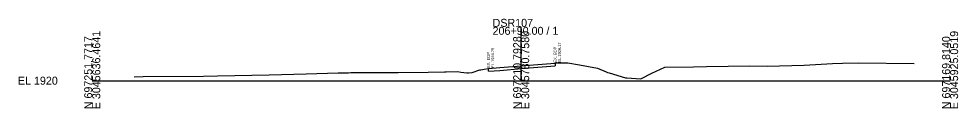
# Model space of a CAD drawing. Extents: x -26 to 19003, y -31 to 24541.
# Drawn here: x 1974.3 to 2302.8, y 16490.3 to 16521.8 of the extents above; entities that cross this region are included whole.
import ezdxf

# ---------------------------------------------------------------- set-up
doc = ezdxf.new("R2010")
doc.units = 0
for name, color, linetype in [('DESIGN - SHEET - Light Grid', 7, 'Continuous'), ('SURVEY - GROUND - Existing Pavement Layer', 7, 'Continuous'), ('SURVEY - GROUND - Existing Pavement Text', 7, 'Continuous'), ('SURVEY - GROUND - Top of Ground', 7, 'Continuous')]:
    doc.layers.add(name, color=color, linetype=linetype)

msp = doc.modelspace()

# ---------------------------------------------------------------- linework, layer by layer
at = {"layer": 'DESIGN - SHEET - Light Grid'}
for p, q in [((2150, 16500), (2150, 16518.91)), ((2000, 16500), (2150, 16500)), ((2150, 16500), (2300, 16500))]:
    msp.add_line(p, q, dxfattribs=at)
at = {"layer": 'SURVEY - GROUND - Existing Pavement Layer'}
for p, q in [((2161.89, 16506.17), (2161.89, 16505.17)), ((2138.55, 16503.29), (2138.55, 16504.29)), ((2138.55, 16503.29), (2142.53, 16503.63)), ((2142.53, 16503.63), (2150.1, 16504.25)), ((2150.1, 16504.25), (2154.33, 16504.59)), ((2154.33, 16504.59), (2161.89, 16505.17))]:
    msp.add_line(p, q, dxfattribs=at)
at = {"layer": 'SURVEY - GROUND - Top of Ground'}
msp.add_lwpolyline([(2014.71, 16501.39), (2017.78, 16501.46), (2038.91, 16501.61), (2043.82, 16501.71), (2061.89, 16502.04), (2074.84, 16502.41), (2085.96, 16502.76), (2089.67, 16502.8), (2090.47, 16502.82), (2094.39, 16502.86), (2098.05, 16502.87), (2099.25, 16502.87), (2100.45, 16502.9), (2106.95, 16502.91), (2117.49, 16503.03), (2123.19, 16503.1), (2123.78, 16503.1), (2127.89, 16503.25), (2128.88, 16502.98), (2130.99, 16502.75), (2131.58, 16502.8), (2132.9, 16502.89), (2135.51, 16503.75), (2135.89, 16503.84), (2137.1, 16504.09), (2138.55, 16504.29), (2142.53, 16504.63), (2150.1, 16505.25), (2154.33, 16505.59), (2161.89, 16506.17), (2162.29, 16506.21), (2162.85, 16506.24), (2165.2, 16506.3), (2166.26, 16506.27), (2170.36, 16505.52), (2176.66, 16504.43), (2179.69, 16503.05), (2180.23, 16502.86), (2180.72, 16502.72), (2186.53, 16500.97), (2186.9, 16500.99), (2191.87, 16500.7), (2195.74, 16502.58), (2200.21, 16504.78), (2210.22, 16504.87), (2214.83, 16504.93), (2229.93, 16505.16), (2236.06, 16505.12), (2248.99, 16505.39), (2258.86, 16506.08), (2262.32, 16506.18), (2267.93, 16506.3), (2287.47, 16506.04)], dxfattribs=at)

# ---------------------------------------------------------------- texts
at = {"layer": 'DESIGN - SHEET - Light Grid'}
for s, p in [('206+90.00 / 1', (2140, 16516.11)), ('DSR107', (2140, 16518.91)), ('EL 1920', (1974, 16498.6))]:
    msp.add_text(s, height=2.8, dxfattribs=at).set_placement(p)
for s, p in [('N 697251.7717', (2000, 16490)), ('E 3045636.4641', (2002.8, 16490)), ('N 697210.7928', (2150, 16490)), ('E 3045780.7580', (2152.8, 16490)), ('N 697169.8140', (2300, 16490)), ('E 3045925.0519', (2302.8, 16490))]:
    msp.add_text(s, height=2.8, rotation=90, dxfattribs=at).set_placement(p)
at = {"layer": 'SURVEY - GROUND - Existing Pavement Text'}
for s, p in [('EL.1926.17', (2163.89, 16506.37)), ('EX. EOP', (2139.05, 16504.49)), ('EL.1924.29', (2140.55, 16504.49)), ('EX. EOP', (2162.39, 16506.37))]:
    msp.add_text(s, height=1, rotation=90, dxfattribs=at).set_placement(p)

doc.saveas('drawing.dxf')
